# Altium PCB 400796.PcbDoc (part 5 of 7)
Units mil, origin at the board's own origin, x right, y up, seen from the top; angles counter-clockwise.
Board outline 2086.61 x 2086.61 mil, 6 copper layers (Top Layer, Mid Layer 1, Mid Layer 2, Mid Layer 3, Mid Layer 4, Bottom Layer), stack 58.818 mil thick; 313 components, 234 nets, 1244 pads, 2538 vias.
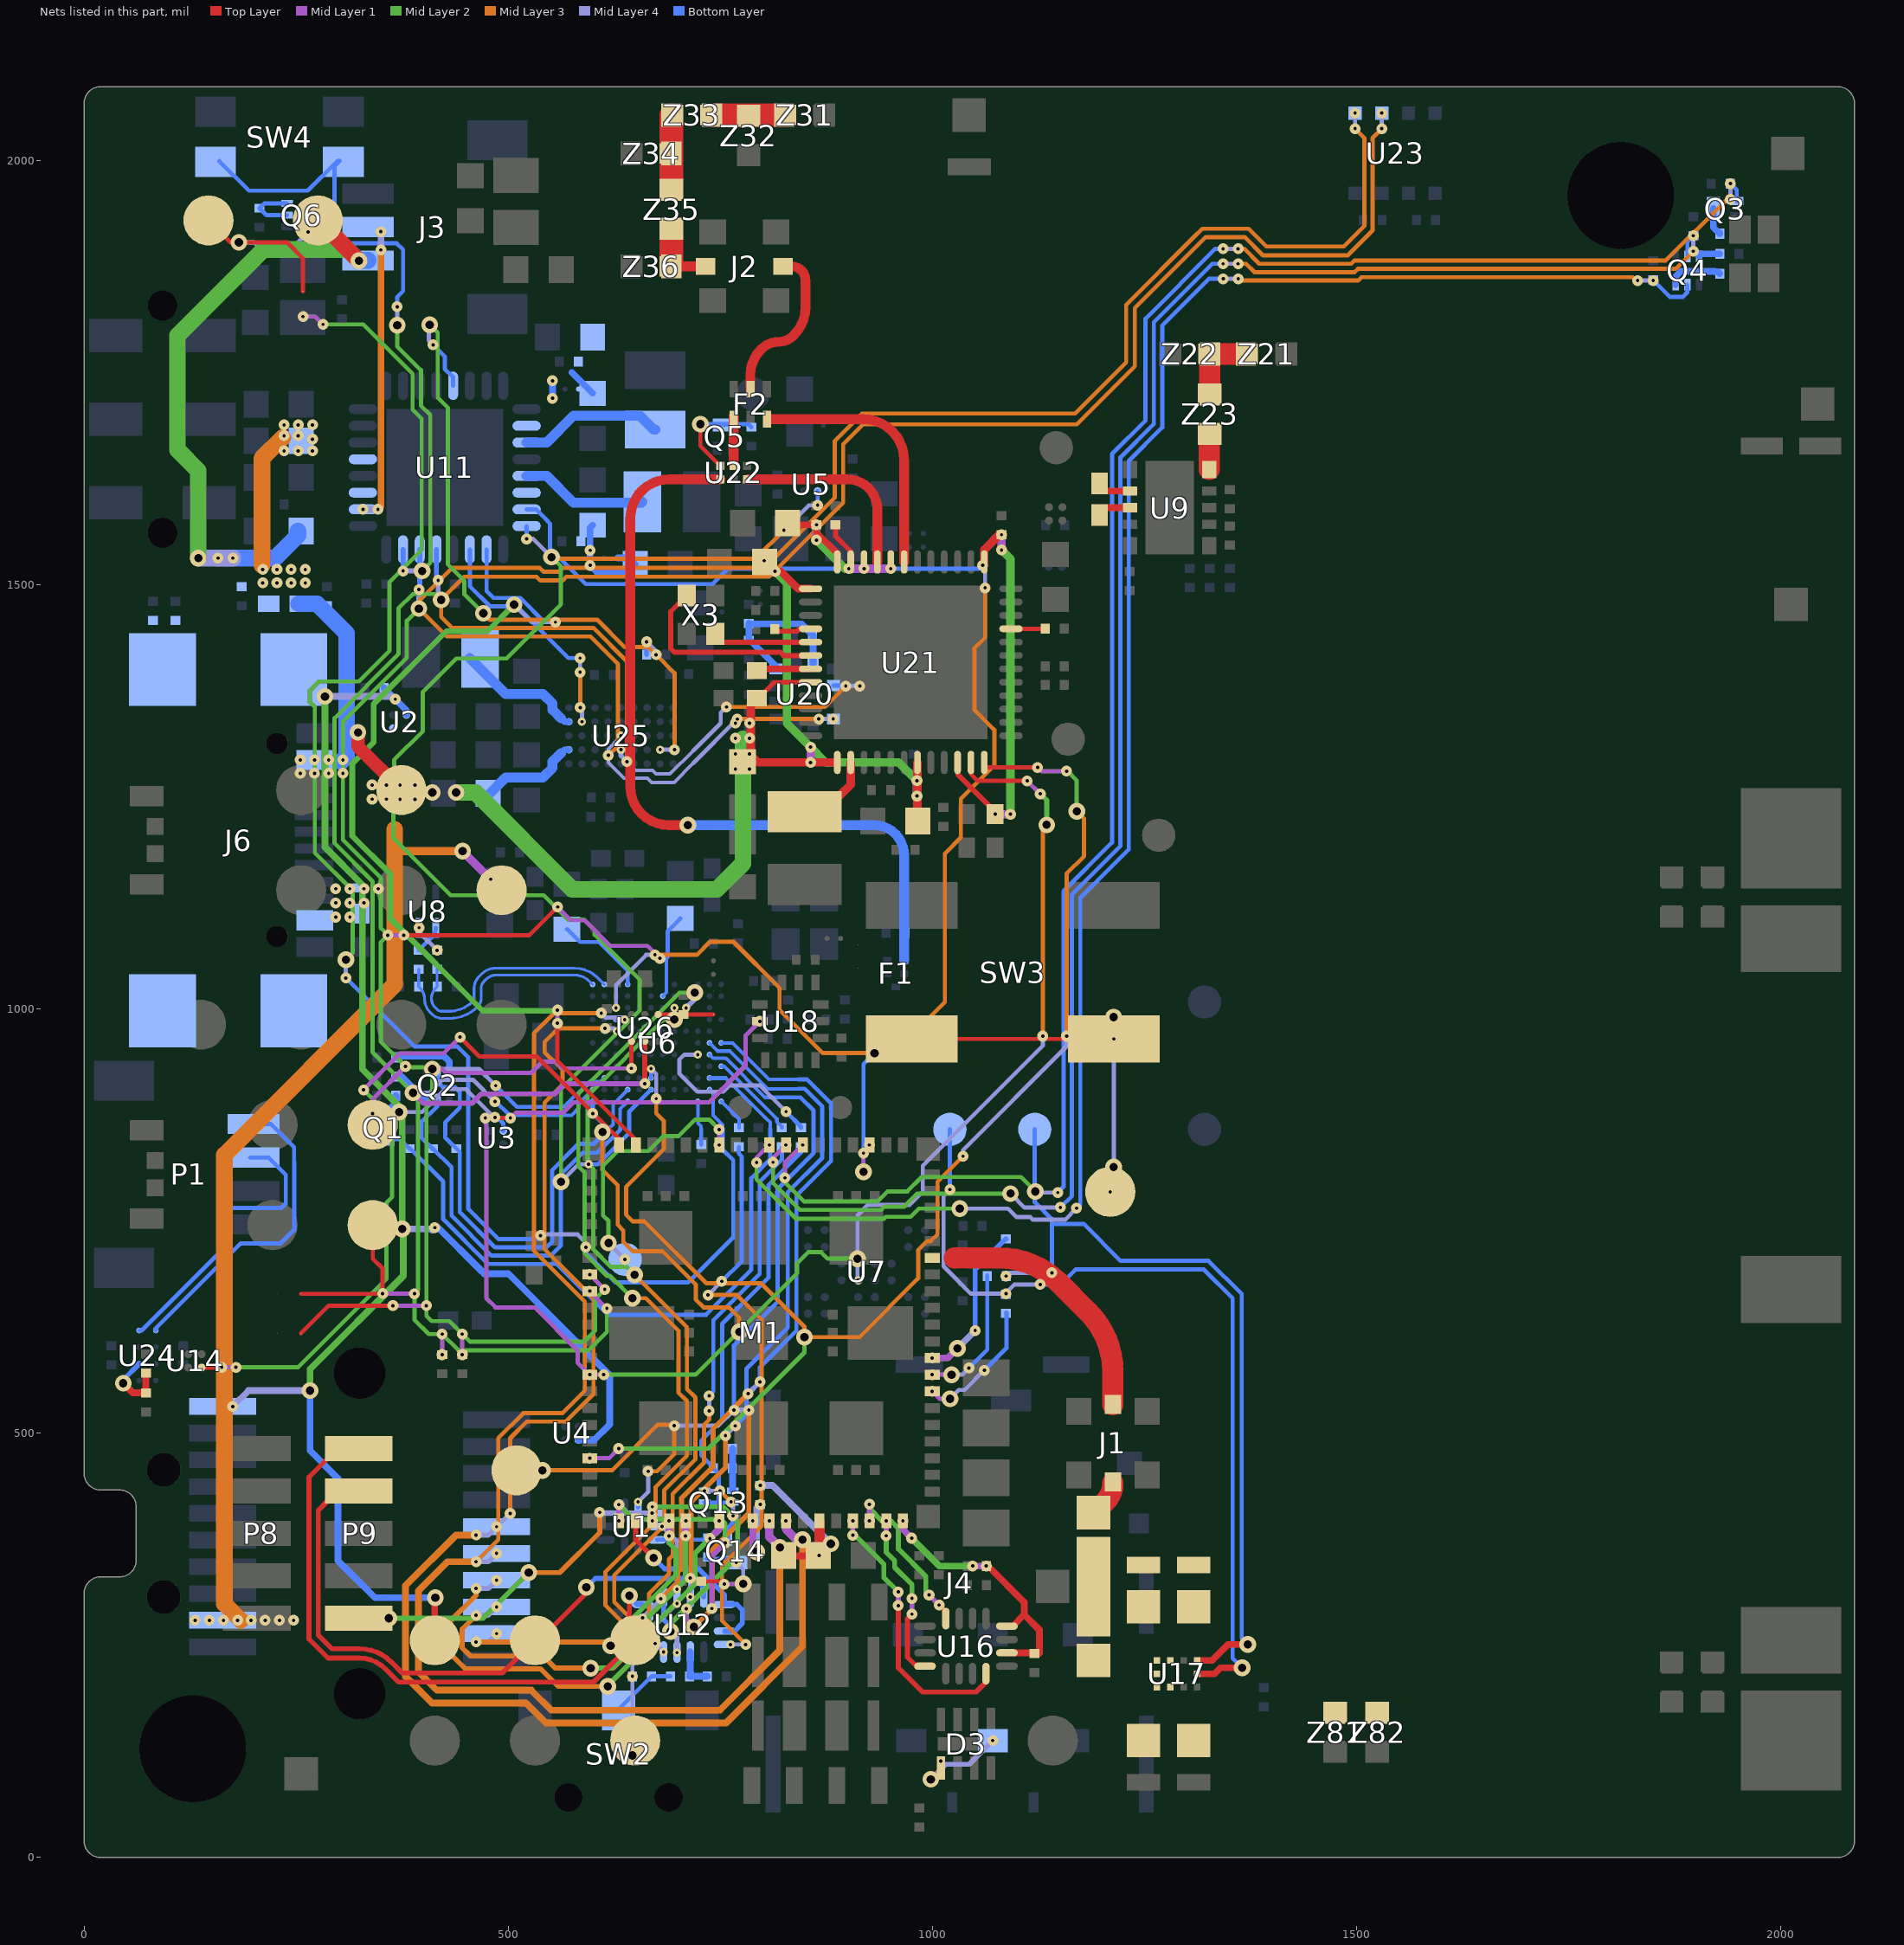
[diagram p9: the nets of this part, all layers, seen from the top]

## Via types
v1: diameter 12.8, hole 3.94, Mid Layer 4 to Bottom Layer, tented both sides, 653 vias
v2: diameter 12.8, hole 3.94, Top Layer to Mid Layer 1, tented both sides, 560 vias
v3: diameter 12.8, hole 3.94, Mid Layer 3 to Mid Layer 4, tented both sides, 388 vias
v4: diameter 19.68, hole 9.84, Mid Layer 1 to Mid Layer 4, tented both sides, 311 vias
v5: diameter 12.8, hole 3.94, Mid Layer 1 to Mid Layer 2, tented both sides, 265 vias
v6: diameter 19.68, hole 9.84, Top Layer to Bottom Layer, tented both sides, 169 vias
v7: diameter 9.84, hole 3.94, Mid Layer 4 to Bottom Layer, tented both sides, 105 vias
v8: diameter 12.8, hole 3.94, Top Layer to Mid Layer 1, tented top, 70 vias
v9: diameter 9.84, hole 3.94, Top Layer to Mid Layer 1, tented both sides, 17 vias

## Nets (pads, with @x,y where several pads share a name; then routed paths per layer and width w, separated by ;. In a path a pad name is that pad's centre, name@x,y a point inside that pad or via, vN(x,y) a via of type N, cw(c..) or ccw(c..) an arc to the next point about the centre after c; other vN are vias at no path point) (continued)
NetC71_2: C71.2 U21.16 | length 44.6
  Top Layer w5.98: C71.2@814.17,1447.43 814.17,1446.84 816,1445.02 840.29,1445.02 841.23,1445.96 843.1,1447.83 U21.16@856.3,1447.83
NetC72_2: C72.2 U21.19 | length 64
  Top Layer w7.87: C72.2@793.11,1398.58 795.13,1400.59 U21.19@856.3,1400.59
NetC87_2: C87.2 C88.2 R26.2 U20.10 U20.12 | length 181.8
  Bottom Layer w7.87: U20.10@815.55,1400.59 815.55,1403.67 783.46,1435.76 R26.2@783.46,1454.33 784.06,1453.74 845.47,1453.74 859.25,1439.96 U20.12@859.25,1406.89
NetC92_2: C92.2 SB10.2 U26.C1 | length 65.1
  Top Layer w4.92: U26.C1@676.7,993.35 676.81,993.24 SB10.2@741.78,993.24
NetC103_2: C103.2 FB1.2 M1.14 R1.1 | length 211
  Top Layer w8: C103.2@827.34,355.52 FB1.2@865.42,355.52
  Top Layer w12: FB1.2@865.42,355.94 v2(866.46,355.94) ; FB1.2@866.81,355.94 M1.14@866.81,396.65
  Mid Layer 1 w8: v2(866.46,355.94) v4(880.18,369.67)
  Mid Layer 4 w8: v1(796.94,438.41) 811.44,438.41 v4(880.18,369.67)
NetCR1_2: CR1.2 F1.4 U22.1 | length 941.3
  Top Layer w11.42: v6(711.61,1216.54) 689.05,1216.54 cw(c689.05,1261.74) 643.84,1261.74 643.84,1577.85 cw(c690.01,1577.85) 690.01,1624.02 U22.1@750,1624.02
  Bottom Layer w11.42: v6(711.61,1216.54) 931.09,1216.54 cw(c931.09,1181.1) 966.53,1181.1 F1.4@966.53,1057.11
NetF2_1: F2.1 U22.5 | length 57.8
  Top Layer w11.42: U22.5@765.75,1641.02 F2.1@765.75,1698.82
NetF2_3: F2.3 U21.7 | length 308
  Top Layer w11.42: F2.3@806.1,1694.88 918.28,1694.88 cw(c918.28,1646.63) 966.54,1646.63 U21.7@966.54,1526.57
NetF2_6: F2.6 J2.1 | length 197.6
  Top Layer w11.42: F2.6@785.43,1730.31 785.43,1747.09 cw(c827.73,1747.09) 797.82,1776.99 798.25,1777.42 cw(c818.88,1756.78) 818.88,1785.97 ccw(c818.88,1809.4) 835.45,1792.83 836.78,1794.16 ccw(c803.96,1826.99) 850.38,1826.99 850.38,1858.31 ccw(c833.59,1858.31) 845.46,1870.18 ccw(c833.99,1858.71) 833.99,1874.93 J2.1@823.92,1874.93
NetJ1_1: J1.1 M1.35 | length 296.3
  Top Layer w25.12: 1026.01,706.64 1078.2,706.64 cw(c1078.2,606.64) 1148.91,677.35 1183.31,642.96 cw(c1112.6,572.24) 1212.6,572.24 J1.1@1212.6,533.86
NetJ1_3: J1.3 Z7.1 | length 44.1
  Top Layer w25.12: Z7.1@1189.72,405.31 1203.3,418.89 ccw(c1180.85,441.34) J1.3@1212.6,441.34
NetJ2_3: J2.3 Z35.1 Z36.1 | length 83.5
  Top Layer w11.42: Z36.1@692.19,1874.93 J2.3@732.58,1874.93
  Top Layer w27.95: Z36.1@692.19,1874.93 Z35.1@692.18,1918.07
NetL1_2: L1.2 U6.B6 | length 100.1
  Bottom Layer w4.13: U6.B6@682.07,1014.96 686.3,1019.19 686.3,1059.33 687.97,1061.01
  Bottom Layer w4.92: 687.97,1061.01 687.97,1091.73 L1.2@702.74,1106.5
NetL2_2: L2.2 U6.A9 | length 108.4
  Bottom Layer w4.92: L2.2@568.88,1093.7 569.86,1093.7 584.8,1078.76 607.19,1078.76 640.73,1045.22 U6.A9@640.73,1028.74
NetL5_1: L5.1 U9.8 | length 38.4
  Top Layer w7.87: L5.1@1196.85,1584.65 1202.76,1590.55 1207.37,1590.55 U9.8@1232.78,1590.55
NetL5_2: L5.2 U9.7 | length 38.4
  Top Layer w7.87: L5.2@1196.85,1616.14 1202.76,1610.24 1207.37,1610.24 U9.7@1232.78,1610.24
NetL6_1: L6.1 U21.26 | length 93.5
  Top Layer w10: L6.1@849.41,1232.15 868.62,1251.36 890.6,1251.36 903.54,1264.31 U21.26@903.54,1290.35
NetM1_2: M1.2 SB6.1 | length 260
  Mid Layer 1 w5.91: v2(630.42,396.65) v5(630.42,415.76) ; v2(739.9,293.4) 739.9,355 v5(755.58,370.67)
  Mid Layer 2 w5.91: v5(630.42,415.76) 647.7,398.48 750.54,398.48 755.58,393.44 v5(755.58,370.67)
NetM1_3: M1.3 U12.5 U12.7 | length 229.6
  Top Layer w5.91: M1.3@650.1,396.65 650.1,374.36 v6(671.32,353.15)
  Bottom Layer w5.91: v6(671.32,353.15) 684.3,340.16 724.31,340.16 754.92,309.55 U12.5@754.92,298.23 769.41,298.23 775.97,291.67 775.97,275.95 766.75,266.73 U12.7@754.92,266.73
NetM1_4: M1.4 U12.1 U12.11 | length 387
  Mid Layer 1 w5.91: v2(669.79,396.65) v5(669.79,413.3)
  Mid Layer 2 w5.91: v5(669.79,413.3) 753.02,413.3 770.25,396.07 770.25,354.65 691.12,275.52 v4(691.12,266.4)
  Mid Layer 4 w5.91: v4(691.12,266.4) 698.82,258.7 v7(698.82,241.43)
  Bottom Layer w5.91: U12.1@683.07,307.09 683.07,280.49 698.82,264.74 U12.11@698.82,242.13 v7(698.82,241.43)
NetM1_10: M1.10 R1.2 | length 106.1
  Mid Layer 1 w8: v2(788.07,396.65) 788.07,364.81 v4(792.64,360.24) ; v4@789.64,357.24 v4@792.64,354.24
  Mid Layer 4 w8: v4@792.64,354.24 v4(792.64,360.24) 792.64,411.67 v1(796.94,415.97)
NetM1_27: M1.27 R27.1 | length 164.8
  Mid Layer 1 w4.92: v2(999.53,549.21) 1008.27,540.47 v4(1020.66,540.47)
  Mid Layer 4 w4.92: v4@1026.67,540.47 v4(1020.66,540.47) 1031.05,550.87 1037.87,550.87 v1(1061.13,574.12)
  Bottom Layer w4.92: v1(1061.13,574.12) 1087.2,600.2 1087.2,642.32 R27.1@1086.61,642.32
NetM1_28: M1.28 R28.1 | length 164.8
  Mid Layer 1 w4.92: v2(999.53,568.9) v4(1022.42,568.9)
  Mid Layer 4 w4.92: v4(1022.42,568.9) 1034.99,568.9 v1(1042.88,576.79)
  Bottom Layer w4.92: v1(1042.88,576.79) 1064.57,598.47 R28.1@1064.57,686.02
NetM1_29: M1.29 R29.1 | length 187.4
  Mid Layer 1 w7.87: v2(999.53,588.58) 1017.96,588.58 v4(1029.38,600)
  Mid Layer 4 w7.87: v4(1029.38,600) 1050.2,620.82 v1(1050.2,621)
  Bottom Layer w5.91: v1(1050.2,621) 1050.2,693.03 1085.91,728.74 R29.1@1086.61,728.74
NetM1_44: M1.44 SW3.2 TP36.1 U6.C10 U11.7 | length 2338
  Top Layer w4.92: SW3.2@975.39,964.57 v2(1213.58,964.57)
  Mid Layer 1 w4.92: v4(918.71,808.12) 918.71,832.57 v2(925.71,839.57) ; v2(1209.43,784.45) 1213.39,788.41 v4(1213.39,813.48) ; v2(1213.58,964.57) v4(1213.58,990.29)
  Mid Layer 3 w4.92: v3(672.79,1063.59) 722.15,1063.59 737.6,1079.03 765.45,1079.03 819.79,1024.69 819.79,998.77 870.75,947.82 v6(931.63,947.82) 941.46,947.82 955.99,962.35 969.12,962.35 1014.46,1007.7 1014.46,1182.95 1033.48,1201.96 1033.48,1247.56 1072.87,1286.96 1072.87,1328.86 1049.47,1352.26 1049.47,1424.87 1062.01,1437.41 v3(1062.01,1496.06)
  Mid Layer 4 w4.92: v7(626.95,1001.18) 626.95,1027.98 662.56,1063.59 v3(672.79,1063.59) ; v4(918.71,808.12) v1(918.71,829.93) ; v1(1059.06,1522.64) 1062.01,1519.68 v3(1062.01,1496.06) ; v4(1213.39,813.48) 1213.58,813.67 v4(1213.58,990.29)
  Bottom Layer w4.92: U11.7@521.65,1588.58 532.48,1588.58 546.26,1574.8 549.1,1571.96 549.1,1542.82 591.43,1500.49 740.65,1500.49 758.86,1518.7 1055.12,1518.7 v1(1059.06,1522.64) ; v1@920.9,828.93 918.71,831.12 918.71,934.9 v6(931.63,947.82)
NetM1_48: M1.48 Q3.1 R44.2 | length 2280.2
  Mid Layer 1 w4.92: v5(825.95,800.89) 825.95,818.55 v2(846.97,839.57)
  Mid Layer 2 w4.92: v5(825.95,800.89) 825.95,795.54 848.37,773.12 935.35,773.12 947.08,784.85 970.32,784.85 987.28,801.8 1104.11,801.8 v4(1121.06,784.85)
  Mid Layer 3 w4.92: v3(1360.24,1895.67) 1367.32,1895.67 1385.03,1877.95 1493.39,1877.95 1497.33,1881.89 1864.17,1881.89 1936.42,1954.13 v3(1940.35,1954.13)
  Mid Layer 4 w4.92: v4(1121.06,784.85) 1122.37,783.54 v1(1147.64,783.54) ; v1(1342.52,1895.67) v3(1360.24,1895.67) ; v3(1940.35,1954.13) v1(1940.35,1972.44)
  Bottom Layer w4.92: v1(1147.64,783.54) 1154.53,790.43 1154.53,1138.78 1211.61,1195.87 1211.61,1653.82 1250.98,1693.19 1250.98,1813.27 1333.38,1895.67 v1(1342.52,1895.67) ; v1(1940.35,1972.44) 1947.83,1964.96 Q3.1@1947.83,1951.77
NetM1_49: M1.49 Q4.5 R46.2 | length 2230.4
  Mid Layer 1 w4.92: v5(812.1,819.26) 812.1,824.38 v2(827.28,839.57)
  Mid Layer 2 w4.92: v5(812.1,819.26) 812.1,794.68 843.6,763.18 939.33,763.18 943.22,767.07 966.75,767.07 982.01,782.33 v4(1091.91,782.33)
  Mid Layer 3 w4.92: v3(1360.24,1877.95) 1369.61,1877.95 1379.45,1868.11 1497.47,1868.11 1501.4,1872.05 1875.98,1872.05 v3(1896.65,1892.72)
  Mid Layer 4 w4.92: v4(1091.91,782.33) 1108.39,765.84 1150.61,765.84 v1(1150.79,766.02) ; v1(1342.52,1877.95) v3(1360.24,1877.95) ; v3(1896.65,1892.72) v1(1896.65,1911.02)
  Bottom Layer w4.92: v1(1150.79,766.02) 1164.37,779.6 1164.37,1134.7 1221.46,1191.79 1221.46,1649.75 1260.83,1689.12 1260.83,1809.2 1329.58,1877.95 v1(1342.52,1877.95) ; Q4.5@1889.76,1886.81 1889.76,1904.13 v1(1896.65,1911.02)
NetM1_50: M1.50 Q4.2 R45.2 | length 2206.4
  Mid Layer 1 w4.92: v5(792.72,818.89) 792.72,824.69 v2(807.6,839.57)
  Mid Layer 2 w4.92: v5(792.72,818.89) 792.72,799.02 839.07,752.67 942.74,752.67 944.93,754.86 974.13,754.86 983.84,764.57 v4(1032.19,764.57)
  Mid Layer 3 w4.92: v3(1360.27,1860.2) 1362.21,1858.27 1501.54,1858.27 1505.48,1862.2 1825.03,1862.2 1828.97,1858.26 v3(1831.1,1858.26)
  Mid Layer 4 w4.92: v4(1032.19,764.57) 1089.09,764.57 1099.09,754.57 1115.32,754.57 1118.3,751.6 1156.22,751.6 v1(1169.74,765.12) ; v1(1342.56,1860.2) v3(1360.27,1860.2) ; v3(1831.1,1858.26) v1(1849.41,1858.26)
  Bottom Layer w4.92: v1(1169.74,765.12) 1170.63,765.12 1174.21,768.7 1174.21,1130.63 1231.3,1187.71 1231.3,1645.67 1270.67,1685.04 1270.67,1805.12 1325.75,1860.2 v1(1342.56,1860.2) ; R45.2@1849.41,1858.65 1868.99,1839.07 1884.44,1839.07 1889.47,1844.1 1889.47,1853.05 Q4.2@1889.76,1853.35
NetM1_53: M1.53 TP23.1 | length 300
  Mid Layer 1 w4.92: v2(748.54,839.57) v5(748.54,857.88)
  Mid Layer 2 w4.92: v4(618.12,724.02) 618.12,750.09 611.59,756.63 611.59,815.23 628.78,832.43 665.09,832.43 682.56,849.9 700.61,849.9 709.72,859 720.3,869.58 736.84,869.58 747.42,859 v5(748.54,857.88)
  Mid Layer 4 w4.92: v4@621.12,721.02 v1(637.42,704.72)
  Bottom Layer w4.92: v1(637.42,704.72) TP23.1@637.8,704.72
NetM1_59: M1.59 U14.B2 | length 884.4
  Top Layer w5: U14.B2@138.56,577.34 162.13,577.34 v2(162.35,577.57) ; v2(443.14,966.77) 465.99,943.92 533.53,943.92 557,920.45 618.45,859 630.43,847.02 M1.59@630.43,839.57
  Mid Layer 1 w5: v2(162.35,577.57) v5(179.09,577.57) ; v5(329.5,904.54) 372.51,947.59 423.97,947.59 v2(443.14,966.77)
  Mid Layer 2 w5: v5(179.09,577.57) 252.17,577.57 356.46,681.86 356.46,771.7 363.23,778.46 363.23,859.19 347.88,874.54 347.88,886.16 v5(329.5,904.54)
NetP1_3: P1.3 U24.A2 | length 346
  Bottom Layer w4.92: U24.A2@64.96,621.06 68.07,621.06 161.91,714.9 161.91,760.93 166.51,765.54 232.67,765.54 237.8,770.66 237.8,804.53 217.52,824.8 P1.3@195.87,824.8
NetP1_4: P1.4 U24.A1 | length 360.1
  Bottom Layer w4.92: U24.A1@84.65,621.06 84.65,623.71 184.36,723.43 231.3,723.43 247.64,739.76 247.64,819.78 247.54,819.88 247.54,836.96 220.32,864.17 P1.4@209.65,864.17
NetP9_10: P9.10 R3.1 TP1.1 U2.B2 U3.B2 U4.B2 | length 2104.4
  Top Layer w7.87: TP1.1@413.39,255.91 413.39,305.46 v6(414,306.08)
  Mid Layer 2 w7.87: v6(266.32,550.11) 266.32,575.37 376.27,685.33 376.27,739.19 v4(374.91,740.55) 374.91,873.57 370.21,878.27 370.21,886.67 328.15,928.73 328.15,1146.14 283.96,1190.33 v4(283.96,1368.11)
  Mid Layer 4 w4.92: v4@370.21,878.27 v4@370.8,878.87 ; v4(371.39,878.27) 398.35,878.27 425.46,905.39 450.13,905.39 477.66,877.86 483.47,872.05 v1(484.25,872.05)
  Mid Layer 4 w7.87: v1(175.2,531.5) 193.81,550.11 v6(266.32,550.11) ; v4(283.96,1368.11) 361.22,1368.11 v1@365.16,1364.17 ; v4(374.91,740.55) 408.97,740.55 410.39,739.13 v1(413.39,742.13)
  Bottom Layer w4.92: v1(484.25,872.05) 487.2,872.05 494.09,865.16 U3.B2@494.09,856.3
  Bottom Layer w7.87: v6(266.32,550.11) 266.32,479.53 299.21,446.64 299.21,349.73 342.86,306.08 v6(414,306.08) ; R3.1@353.74,1377.95 379.92,1351.77 U2.B2@379.92,1346.46 ; v1(413.39,742.13) 417.32,742.13 467.03,692.42 471.47,687.98 500.01,687.98 619.59,568.41 619.59,510.33 601.38,492.13 U4.B2@582.68,492.13
  other v1: 366.83,1364.86
NetQ1_1: Q1.1 R41.2 U6.J2 | length 834.5
  Bottom Layer w4.13: 756.44,918.5 803.73,871.21 808.63,866.31 808.63,859
  Bottom Layer w4.92: Q1.1@361.22,846.46 372.64,846.46 R41.2@383.86,835.24 ; R41.2@384.26,835.63 423.23,796.66 423.23,752.23 476.15,699.3 557.33,699.3 617.04,639.59 733.21,639.59 786.38,692.75 786.38,800.53 808.63,822.79 808.63,859 ; U6.J2@737.19,918.5 756.44,918.5
NetQ1_3: Q1.3 R20.1 | length 29.9
  Bottom Layer w7.87: Q1.3@352.36,874.02 367.52,889.17 R20.1@367.52,897.64
NetQ2_2: Q2.2 R38.2 U6.K9 | length 554.7
  Bottom Layer w4.13: 618.78,859 623.53,863.75 623.53,887.53 631.18,895.18 U6.K9@640.73,904.72
  Bottom Layer w4.92: Q2.2@416.78,926.55 416.78,913.75 422.68,907.85 437.06,907.85 442.86,902.05 442.86,883.24 425.67,866.05 425.67,851.46 425.59,851.38 425.59,848.52 ; 425.67,848.52 442.91,831.28 442.91,760.38 484.31,718.99 544.79,718.99 551.82,726.01 551.82,758.34 551.82,809.99 582.81,840.99 600.77,840.99 618.78,859
NetQ2_3: Q2.3 R21.1 | length 78.6
  Bottom Layer w7.87: R21.1@367.52,942.91 367.52,944.39 424.16,944.39 430.56,937.99 Q2.3@430.56,926.55
NetQ2_5: Q2.5 R42.2 U6.L9 | length 525.6
  Bottom Layer w4.13: 631.88,859 631.88,882.09 U6.L9@640.73,890.95
  Bottom Layer w4.92: R42.2@410.98,834.8 397.64,848.14 397.64,866.45 416.78,885.6 Q2.5@416.78,893.08 ; R42.2@411.42,835.24 433.07,813.58 433.07,756.3 480.23,709.14 550.03,709.14 562.04,721.15 562.04,754.31 562.04,805.03 587.49,830.47 604.79,830.47 631.88,857.56 631.88,859
NetQ2_6: Q2.6 R19.1 | length 46.7
  Bottom Layer w7.87: R19.1@367.52,920.28 374.47,920.28 401.67,893.08 Q2.6@403,893.08
NetQ3_3: Q3.3 R12.1 | length 33.9
  Bottom Layer w7.87: Q3.3@1920.28,1942.91 1920.28,1920.87 R12.1@1927.76,1913.39 R12.1@1927.76,1914.69
NetQ4_3: Q4.3 R14.1 | length 69.4
  Bottom Layer w7.87: Q4.3@1875.98,1853.35 1875.98,1862.92 1882.16,1869.09 1897.37,1869.09 ; 1893.43,1869.09 1921.77,1869.09 1922.75,1868.11 1926.38,1868.11 1927.76,1866.73 R14.1@1927.76,1866.14
NetQ4_6: Q4.6 R13.1 | length 27.2
  Bottom Layer w7.87: Q4.6@1903.54,1886.81 1903.54,1889.76 R13.1@1927.76,1889.76
NetQ5_3: Q5.3 R62.2 U22.6 | length 120.9
  Top Layer w4.92: v6(726.38,1688.98) 726.38,1663.39 U22.6@750,1639.76
  Bottom Layer w4.92: v6(726.38,1688.98) 753.94,1688.98 Q5.3@754.92,1687.99 ; Q5.3@754.92,1688.98 782.87,1688.98 R62.2@786.42,1685.43
NetQ6_2: Q6.2 Q6.3 R64.1 | length 70.7
  Bottom Layer w4.92: Q6.2@239.33,1935.22 215.12,1935.22 R64.1@206.85,1943.49 212.37,1949 Q6.3@239.33,1949
NetQ6_6: Q6.6 SB7.2 TP35.1 | length 270.3
  Top Layer w4.92: TP35.1@146.68,1929.13 172.66,1903.16 v6(182.53,1903.16) 239.21,1903.16 258.09,1884.28 SB7.2@258.09,1845.69
  Mid Layer 4 w4.92: v6(182.53,1903.16) 200.57,1903.16 205.19,1898.53 247.24,1898.53 v7(263.98,1915.27)
  Bottom Layer w4.92: v7(263.98,1915.27) 270.15,1921.44 Q6.6@272.8,1921.44
NetQ13_2: Q13.2 Q13.5 R16.2 R107.1 R108.1 U1.5 | length 619.6
  Bottom Layer w4.92: U1.5@675.4,374.26 675.55,374.41 734.2,374.41 748.03,388.25 748.03,418.31 ; Q13.2@731.3,418.31 748.03,418.31 ; Q13.5@764.76,418.31 748.03,418.31 ; R16.2@844.97,837.4 844.97,830.82 806.81,792.66 806.81,683.45 752.08,628.72 752.08,515.95 727.49,491.36 727.49,473.88 741.84,459.53 R107.1@741.84,458.82 748.03,452.63 748.03,418.31
  Bottom Layer w5.91: Q13.5@764.76,418.31 Q13.5@765.71,419.25
NetQ13_3: Q13.3 Q13.6 Q14.1 | length 86.1
  Mid Layer 3 w4.92: v3(749.52,432.09) v3(762.61,419)
  Mid Layer 4 w4.92: v7(731.3,432.09) v3(749.52,432.09) ; v3(762.61,419) 764.76,416.84 v1(764.76,402.53)
  Bottom Layer w4.92: Q14.1@758.86,375 758.86,388.78 764.76,394.69 v1(764.76,402.53) Q13.6@764.76,404.53
NetQ13_4: Q13.4 R106.2 R107.2 | length 49.8
  Bottom Layer w8: R106.2@764.28,481.68 R107.2@764.28,458.82 764.28,432.57 Q13.4@764.76,432.09
NetQ14_3: Q14.3 R2.1 R108.2 | length 116.9
  Top Layer w4.92: R2.1@727.55,325.5 751.28,325.5 v2(754.61,322.16)
  Mid Layer 1 w4.92: v2(754.61,322.16) v4@775.77,322.16 ; v4@775.77,321.17 v4(776.94,322.35)
  Mid Layer 4 w4.92: v1(768.73,347.44) 776.94,339.23 v4(776.94,322.35)
  Bottom Layer w4.92: R108.2@733.41,351.97 764.2,351.97 v1(768.73,347.44)
NetR4_2: R4.2 U12.8 | length 699.5
  Mid Layer 3 w4.92: v3(735.39,662.74) 769.53,662.74 798.69,633.57 798.69,390.92 751.82,344.04 751.82,279 v3(779.83,250.98)
  Mid Layer 4 w4.92: v3(735.39,662.74) v1(751.55,678.9) ; v7(761.92,250.98) v3(779.83,250.98)
  Bottom Layer w4.92: v1(751.55,678.9) 775.24,702.59 775.24,825.91 771.84,829.31 R4.2@771.84,837.4
NetR5_2: R5.2 R15.1 U24.C2 | length 85.8
  Top Layer w6: v6@45.95,559.14 v6(46.24,558.84)
  Top Layer w8: v6(46.24,558.84) 57.53,547.55 R15.1@72.92,547.55 72.97,547.61 R5.2@72.97,570.96
  Bottom Layer w6: v6(46.24,558.84) 46.24,562.98 U24.C2@64.96,581.69
NetR6_2: R6.2 U12.12 | length 667.3
  Mid Layer 3 w4.92: v3(673.09,252.14) 665.83,259.4 665.83,310.85 689.4,334.43 689.4,351.62 693.81,356.03 693.81,428.34 730.74,465.28 730.74,509.71 736.76,515.73 v3(736.76,526.22)
  Mid Layer 4 w4.92: v3(673.09,252.14) v7(683.07,242.13) ; v3(736.76,526.22) v1(736.76,543.89)
  Bottom Layer w4.92: v1(736.76,543.89) 741.76,548.88 741.76,633.04 796.36,687.64 796.36,796.13 822.48,822.25 R6.2@822.48,837.4
NetR11_2: R11.2 U6.L3 | length 52.6
  Bottom Layer w4.13: U6.L3@723.41,890.95 723.41,865.56 727.38,861.59 727.38,859
  Bottom Layer w4.92: R11.2@727.38,839.96 727.38,859
NetR17_1: R17.1 R32.2 U12.10 | length 50
  Bottom Layer w8: U12.10@714.57,242.13 714.57,214.45 R17.1@713.58,213.46 R32.2@734.53,213.46
NetR17_2: R17.2 R18.1 SW2.2 | length 78.6
  Bottom Layer w4.92: SW2.2@629.92,173.23 629.92,174.48 R18.1@668.9,213.46 R17.2@691.14,213.46
NetR18_2: R18.2 TP28.1 U1.4 U12.2 | length 281.8
  Mid Layer 4 w4.92: v6(646.39,120.22) v1(646.39,213.53) 646.39,246.66 v7(698.82,299.09) ; v7(681.4,390.01) 698.82,372.59 v7(698.82,316.09)
  Bottom Layer w4.92: v1(646.39,213.53) R18.2@646.46,213.46
NetR31_2: R31.2 U8.7 | length 34.8
  Mid Layer 4 w4.92: v1(394.95,1095.6) ccw(c407.8,1095.6) 398.71,1086.51 v1(416.21,1069.01)
NetR34_2: R34.2 U8.6 | length 32.9
  Bottom Layer w4.92: R34.2@394.47,1069.01 394.58,1069.01 404.71,1079.14 ; 405.49,1079.93 409.82,1084.26 ccw(c398.68,1095.4) U8.6@414.44,1095.4
NetSB6_2: SB6.2 TP5.1 U1.2 U6.G2 | length 1276.8
  Top Layer w4.92: TP5.1@509.68,456.22 v6(540.35,456.22)
  Top Layer w5.91: v2(709.88,293.09) 712.34,293.09 SB6.2@712.34,293.4
  Mid Layer 1 w5.91: v2@709.92,293.05 v2(709.88,293.09) 709.88,280.73 v4(718.88,271.73)
  Mid Layer 3 w4.92: v6(540.35,456.22) 622.47,456.22 676.12,509.87 694.52,509.87 v3(695.67,508.72) 695.67,475.24 675.49,455.06 v3(664.81,455.06)
  Mid Layer 3 w5.91: v4(718.88,271.73) 740.54,293.39 740.54,362.66 783.5,405.63 783.5,422.88 v3(783.5,527.16)
  Mid Layer 4 w4.92: v7(653,418.98) 664.81,430.79 v3(664.81,455.06) ; v3(695.67,508.72) 747.53,508.72 v1(765.97,527.16)
  Mid Layer 4 w5.91: v1(765.97,527.16) v3(783.5,527.16)
  Bottom Layer w4.13: U6.G2@737.19,946.06 741.42,941.83 756,941.83 756.44,941.39 757.17,941.39 802.88,895.68 842,895.68
  Bottom Layer w4.92: v6@540.01,455.88 v6(540.35,456.22) ; U1.2@653,412.41 v7(653,418.98) ; v1(765.97,527.16) 765.97,603.57 817.58,655.18 817.58,787.85 859.75,830.01 859.75,880.34 844.41,895.68 842,895.68
NetSB7_1: SB7.1 U6.K2 | length 1909.1
  Mid Layer 1 w4.92: v2(258.12,1815.67) 272.53,1815.67 v5(281.69,1806.5)
  Mid Layer 2 w4.92: v5(281.69,1806.5) 328.92,1806.5 387.23,1748.2 387.23,1706.15 397.94,1695.44 397.94,1540.82 360.12,1503.01 360.12,1421.97 323.98,1385.83 276.86,1385.83 266.27,1375.24 266.27,1361.22 271.96,1355.53 271.96,1183.94 316.66,1139.24 316.66,1066.07 v4(308.62,1058.03)
  Mid Layer 4 w4.92: v1(308.62,1036.34) v4(308.62,1058.03) ; v1(538.02,732.79) 539.48,734.25 581.79,734.25 591.43,724.61 v1(591.43,719.14)
  Bottom Layer w4.13: U6.K2@737.19,904.72 741.42,900.49 741.42,886.99 741.42,874.69 752.66,863.45 752.66,859
  Bottom Layer w4.92: v1@308.62,1035.34 v1@309.08,1034.89 ; v1(308.62,1036.34) 389.26,955.71 439.96,955.71 452.76,942.91 452.76,764.46 488.38,728.83 534.05,728.83 v1(538.02,732.79) ; v1(591.43,719.14) 591.43,712.41 626.29,677.55 711.9,677.55 727.85,693.51 765.08,730.74 765.08,821.75 752.66,834.17 752.66,859
NetU6_F1: U6.F1 U12.15 | length 857
  Mid Layer 3 w5.91: v3(679.9,304.91) 699.74,324.76 699.74,335.91 704.23,340.4 704.23,423.4 741.4,460.56 741.4,505.27 v3(782.6,546.46)
  Mid Layer 4 w5.91: v7(658.46,282.48) 679.9,303.91 v3(679.9,304.91) ; v3(782.6,546.46) v1(796.62,560.49)
  Bottom Layer w4.13: U6.F1@750.97,959.84 751.06,959.74 764.43,959.74 807.2,916.97 842,916.97
  Bottom Layer w4.92: v1(796.62,560.49) 796.62,577.73 839.65,620.75 839.65,779.86 880.37,820.58 880.37,888.67 852.07,916.97 842,916.97
NetU6_F2: U6.F2 U12.3 | length 806.2
  Mid Layer 3 w5.91: v3(714.57,329.18) 715.31,329.93 715.31,418.75 755.98,459.43 v3(755.98,497.12)
  Mid Layer 4 w4.92: v3(755.98,497.12) v1(767.52,508.66)
  Mid Layer 4 w5.91: v7(714.57,307.09) v3(714.57,329.18)
  Bottom Layer w4.13: U6.F2@737.19,959.84 746.73,950.3 761.07,950.3 805.55,905.82 842,905.82
  Bottom Layer w4.92: v1(767.52,508.66) 780.71,521.85 780.71,575.73 829.43,624.45 829.43,783.89 870.12,824.58 870.12,884.84 849.14,905.82 842,905.82
NetU9_5: U9.5 Z23.1 | length 41.4
  Top Layer w25.12: U9.5@1326.28,1635.57 1326.28,1676.28 Z23.1@1326.77,1676.77
NetU12_13: U12.13
NetU21_9: U21.9 U22.3 | length 234.8
  Top Layer w11.42: U22.3@782.48,1624.02 899.61,1624.02 cw(c899.61,1588.58) 935.04,1588.58 U21.9@935.04,1526.57
NetU21_17: U21.17 X3.1 | length 118
  Top Layer w6: X3.1@739.96,1436.02 743.9,1432.09 U21.17@856.3,1432.09
NetU21_18: U21.18 X3.3 | length 239.9
  Top Layer w6: X3.3@710.43,1487.2 710.43,1485.24 702.61,1477.41 700.64,1477.41 691.46,1468.23 691.46,1424.56 695.88,1420.13 695.99,1420.13 696.03,1420.09 820.94,1420.09 824.69,1416.34 U21.18@856.3,1416.34
NetZ1_2: Z1.2 Z2.2 Z81.1 Z82.1
NetZ5_1: Z5.1 Z6.1 Z7.2 | length 85.8
  Top Layer w25.12: Z5.1@1189.37,277.17 Z7.2@1189.37,363.01
NetZ21_1: Z21.1 Z22.1 Z23.2 | length 89.5
  Top Layer w25.12: Z23.2@1326.77,1724.8 1326.77,1771.26 Z22.1@1327.17,1771.65 Z21.1@1369.68,1771.65
NetZ31_1: Z31.1 Z32.2 Z33.2 | length 130.4
  Top Layer w27.95: Z32.2@785.43,2053.15 Z33.2@740.21,2053.15 Z31.1@825.39,2053.15
NetZ33_1: Z33.1 Z34.1 Z35.2 | length 87.1
  Top Layer w27.95: Z35.2@692.18,1966.1 Z34.1@692.18,2007.92 Z33.1@692.18,2053.15
nPM60_ENABLE: R9.2 U11.29 U25.B2 | length 844.6
  Mid Layer 2 w4.92: v4(407.48,1806.1) 416.83,1796.75 416.83,1720.41 428.72,1708.52 428.72,1523.98 442.31,1510.39 448.08,1504.63 448.08,1488.68 v4(470.59,1466.17)
  Mid Layer 3 w4.92: v4(470.59,1466.17) 478.29,1458.47 604.81,1458.47 637.09,1426.18 665.35,1426.18 v3(674.21,1417.32) 695.91,1395.62 v3(695.91,1305.32)
  Mid Layer 4 w4.92: v4@406.5,1804.13 406.5,1787.4 v1(411.42,1782.48) ; v1(662.99,1432.48) 674.21,1421.26 v3(674.21,1417.32) ; v7(678.94,1305.32) v3(695.91,1305.32)
  Bottom Layer w4.92: v1(411.42,1782.48) 425.2,1768.7 425.2,1754.03 435.04,1744.19 U11.29@435.04,1734.25 ; R9.2@662.99,1417.32 v1(662.99,1432.48)
nPM60_READY: U11.11 U25.H4 | length 283.4
  Mid Layer 3 w4.92: v3(584.65,1396.65) 584.84,1396.46 v3(584.84,1355.11)
  Mid Layer 4 w4.92: v3(584.65,1396.65) v1(584.65,1413.39) ; v7(586.81,1338.39) v3@586.81,1355.11
  Bottom Layer w4.92: U11.11@454.72,1541.34 454.72,1498.03 478.44,1474.31 510.03,1474.31 570.96,1413.39 v1(584.65,1413.39)
nPM1300_INT: M1.58 U11.10 | length 1137.6
  Top Layer w4.92: v2(558,983.07) 558,938.34 650.12,846.23 M1.58@650.12,839.57
  Mid Layer 1 w4.92: v2(558,983.07) v5(558,998.47)
  Mid Layer 2 w6.69: v4(506.78,1476.32) 475.46,1445 427.09,1445 341.54,1359.44 341.54,1314.38 316.14,1288.98 316.14,1203.83 360.97,1158.99 360.97,1106.61 469.78,997.8 557.34,997.8 v5(558,998.47)
  Mid Layer 4 w4.92: v4(506.78,1476.32) 527.39,1455.71 v1(555.53,1455.71)
  Bottom Layer w4.92: U11.10@474.41,1541.34 474.41,1492.27 482.52,1484.15 514.11,1484.15 542.55,1455.71 v1(555.53,1455.71)
NTC: J3.2 U11.18 | length 346.4
  Mid Layer 3 w7.87: v3(346.46,1588.58) 349.9,1592.03 v3(349.9,1894.19)
  Mid Layer 4 w7.87: v1(328.74,1588.58) v3(346.46,1588.58) ; v3(349.9,1894.19) v1(349.9,1915.85)
P0.08/TRACEDATA3: M1.12 P9.15 U6.E10 | length 1712.9
  Mid Layer 1 w9.84: v2(827.27,396.65) 827.27,386.86 839.67,374.46 v4(846.78,374.46)
  Mid Layer 3 w4.92: v3(502.24,405.36) 502.24,494.1 521.83,513.69 568.02,513.69 600.4,546.07 600.4,658.83 542.75,716.48 542.75,889.39 557,903.64 563.86,910.5 563.86,928.52 557,935.38 553.05,939.33 551.98,939.33 542.75,948.57 542.75,960.95 558.77,976.96 v3(613.97,976.96)
  Mid Layer 3 w8: v3(462.13,379.92) 438.45,379.92 378.94,320.41 378.94,213.25 410.17,182.02 520.78,182.02 544.21,158.59 756.67,158.59 846.78,248.7 v4(846.78,374.46)
  Mid Layer 4 w4.92: v1(486.22,389.73) 486.62,389.73 v3(502.24,405.36) ; v3@612.97,976.96 v3@613.47,976.46 ; v3(613.97,976.96) 624.61,976.96 v7(627.95,973.62)
  Mid Layer 4 w6: v3(462.13,379.92) 476.41,379.92 v1(486.22,389.73)
P0.09/TRACEDATA2: M1.11 P9.16 U6.D10 | length 1695.5
  Mid Layer 1 w9.84: v2(807.58,396.65) 807.58,377.8 v4(820.08,365.3)
  Mid Layer 3 w4.92: v3(462.13,348.46) 488.29,374.63 488.29,494.18 517.67,523.57 563.88,523.57 590.32,550 590.32,654.92 530.26,714.97 530.26,971.23 553.95,994.92 557,994.92 v3(609.63,994.92)
  Mid Layer 3 w8: v3(462.13,348.46) 428.33,348.46 393.99,314.12 393.99,219.14 415.97,197.16 527.08,197.16 550.71,173.53 749.45,173.53 820.08,244.17 v4(820.08,365.3)
  Mid Layer 4 w4.92: v3(609.63,994.92) 614.82,989.73 634.77,989.73 v7(637.22,987.28)
  Mid Layer 4 w6: v3(462.13,348.46) 476.41,348.46 v1(486.22,358.27)
  Bottom Layer w4.92: U6.D10@626.95,987.4 v7@637.1,987.4
  Bottom Layer w9.84: v7@637.1,987.4 v7(637.22,987.28)
P0.10/TRACEDATA1: M1.8 P9.17 U6.C5 | length 1550.1
  Mid Layer 1 w8: v5(737.55,375.91) 748.53,386.89 v2(748.53,396.65)
  Mid Layer 2 w4.92: v4(648.92,686.75) 639.68,695.98 620.72,695.98 600.28,716.43 600.28,811.27 593.67,817.88 593.67,859 593.67,897.78 683.23,987.34 v4(695.85,987.34)
  Mid Layer 2 w6: v4(617.27,201.63) 617.27,202.88 650.89,236.5 650.89,252.8 720.23,322.14 720.23,358.59 v5(737.55,375.91)
  Mid Layer 3 w4.92: v4(617.27,201.63) 654.9,239.26 654.9,271.14 624.83,301.21 624.83,332.51 683.73,391.41 683.73,432.53 720.7,469.5 720.7,542.04 710.63,552.11 710.63,625.04 v4(648.92,686.75)
  Mid Layer 3 w6: v3(462.13,316.96) 462.13,308.95 430.73,277.55 430.73,241.03 449.32,222.44 538.03,222.44 558.84,201.63 v4(617.27,201.63)
  Mid Layer 4 w6: v3(462.13,316.96) 476.41,316.96 v1(486.22,326.77) ; v4(695.85,987.34) v7(695.85,1001.18)
P0.11/TRACEDATA0: M1.6 P9.18 U6.C4 | length 1506.9
  Mid Layer 1 w8: v5(708.98,378.95) v2@708.98,396.65
  Mid Layer 2 w4.92: v4(646.3,659.13) 634.09,671.34 634.09,671.55 620.35,685.3 616.53,685.3 590.08,711.74 590.08,807.03 582.53,814.58 582.53,859 582.53,899.86 701.81,1019.14 v4(719.64,1019.14)
  Mid Layer 2 w6: v4(597.16,223.16) 621.94,223.16 639.79,241.01 639.79,258.04 708.98,327.22 v5(708.98,378.95)
  Mid Layer 3 w4.92: v4(597.16,223.16) 624.61,223.16 644.71,243.26 644.71,266.95 614.58,297.08 614.58,336.78 673.66,395.87 673.66,436.72 710.59,473.65 710.59,537.93 700.6,547.91 700.6,620.71 662.18,659.13 v4(646.3,659.13)
  Mid Layer 3 w6: v3(462.13,285.47) 445.74,269.08 445.74,247.1 455.49,237.36 541.3,237.36 555.5,223.16 v4(597.16,223.16)
  Mid Layer 4 w6: v3(462.13,285.47) 476.41,285.47 v1(486.22,295.28) ; v7(709.63,1001.18) 719.64,1011.19 v4(719.64,1019.14)
  other v2: 709.16,396.65
P0.12/TRACECLK: M1.5 P9.19 | length 370.9
  Mid Layer 1 w8: v5(689.47,378.95) v2(689.47,396.65)
  Mid Layer 2 w6: v4(620.56,249.43) 620.56,255.92 697.5,332.86 697.5,362.65 689.47,370.68 v5(689.47,378.95)
  Mid Layer 3 w6: v3(462.13,253.97) 527.19,253.97 616.02,253.97 v4(620.56,249.43)
  Mid Layer 4 w6: v3(462.13,253.97) 476.41,253.97 v1(486.22,263.78)
PALDO: C62.1 C63.2 U21.8 U21.10 U21.12 | length 210.5
  Top Layer w7.87: C63.2@830.17,1579.73 839.41,1570.48 v2(863.19,1570.48) 863.19,1561.19 887.8,1536.58 U21.12@887.8,1526.57
  Mid Layer 1 w9.84: v5(863.19,1552.47) v2(863.19,1570.48) ; v5(901.29,1518.7) v2(919.29,1518.7) v2(950.79,1518.7)
  Mid Layer 2 w9.84: v5(863.19,1552.47) 896.96,1518.7 v5(901.29,1518.7)
PVSS1: C9.1 C47.1 C52.1 NT1.2 U11.2 | length 55.5
  Bottom Layer w7.87: v1(552.17,1719.49) v1(552.17,1740.16) ; 574.8,1750 C47.1@599.41,1725.39
PVSS2: C48.1 C53.1 C74.1 NT2.2 U11.6 | length 132.5
  Bottom Layer w7.87: C48.1@599.41,1569.88 596.46,1566.93 v1(596.46,1540.35) v1(596.46,1522.64) 604.33,1514.76 640.75,1514.76 C53.1@649.61,1523.62 641.73,1531.5 NT2.2@628.94,1531.5
PWRIOVDD: C41.2 C42.2 U21.1 U21.34 | length 480
  Top Layer w6: U21.34@1029.53,1290.35 1029.89,1290 1029.89,1276.15 1076.7,1229.33 v2(1073.82,1229.33)
  Top Layer w10: U21.1@1061.02,1526.57 1061.02,1541.23 1078.47,1558.67 v2(1081.42,1558.67) 1082.01,1558.67 1082.33,1558.35 C41.2@1082.33,1557.76 ; C41.2@1080.52,1557.76 1080.52,1558.35 C41.2@1080.83,1558.67
  Mid Layer 1 w9.84: v2(1073.82,1229.33) v5(1091.82,1229.33) ; v5(1081.42,1540.67) v2(1081.42,1558.67)
  Mid Layer 2 w9.84: v5(1081.42,1540.67) 1091.82,1530.26 v5(1091.82,1229.33)
QSPI_CLK: M1.73 U6.L12 U7.E3 U18.13 U21.35 | length 2338.8
  Top Layer w4.92: v2(472.96,871.33) v2(502.53,871.33) ; U21.35@1045.28,1290.35 1045.28,1276.57 1053.15,1268.7 1064.16,1268.7 v2(1111.62,1268.7)
  Mid Layer 1 w4.92: v2(472.96,871.33) 472.96,865.11 474.06,864.02 474.06,659.19 485.06,648.19 530.92,648.19 581.71,597.4 581.71,583.18 v2(595.98,568.9) v5(612.6,568.9) ; v2(502.53,871.33) 508.7,877.51 564.46,877.51 576.71,889.76 ; v2(1111.62,1268.7) v5(1127.02,1253.3)
  Mid Layer 1 w5: 576.71,889.76 736.33,889.76 779.73,933.16 779.73,968.63 v2(796.48,985.38)
  Mid Layer 2 w5: v5(612.6,568.9) 720.81,568.9 840.46,688.55 840.46,700.36 853.38,713.27 868.84,713.27 876.49,705.63 v4(911.6,705.63)
  Mid Layer 2 w5.91: v5(1127.02,1253.3) 1134.57,1245.75 v4(1134.57,1216.82)
  Mid Layer 3 w4.92: v4(610.98,854.87) 610.98,810.13 628.93,792.17 628.93,745.56 635.67,738.82 635.67,725.14 646.35,714.46 681.71,714.46 720.91,675.25 720.91,657.45 730.21,648.15 760.12,648.15 772.15,636.13 v4(772.15,619.23) ; v3(1129.95,967.86) 1129.95,1212.21 v4(1134.57,1216.82)
  Mid Layer 4 w4.92: v1(599.51,876.64) 610.98,865.17 v4(610.98,854.87) ; v7(912.4,680.12) 911.6,680.92 v4(911.6,705.63) 911.6,756.74 923.98,769.12 973.07,769.12 988.47,784.52 988.47,814.93 1129.95,956.41 v3(1129.95,967.86)
  Bottom Layer w5.91: v1@599.39,879.52 U6.L12@599.39,890.95
QSPI_SS: M1.78 U6.J7 U21.36 | length 1759.6
  Top Layer w4.92: U21.36@1061.02,1284.45 v2(1123.89,1284.45)
  Mid Layer 1 w4.92: v2(595.98,470.47) 618.77,470.47 v5(630.15,481.85) ; v2(1123.89,1284.45) 1128.32,1280.02 v5(1157.96,1280.02)
  Mid Layer 2 w4.92: v5(1157.96,1280.02) 1159.11,1280.02 1169.99,1269.15 v4(1169.99,1232.94)
  Mid Layer 2 w5: v5(630.15,481.85) 735.78,481.85 849.04,595.11 v4(849.04,613.15)
  Mid Layer 3 w4.92: v3(674.4,894.17) 674.4,876.93 683.45,867.87 683.45,834.8 638.79,790.14 638.79,757.44 646.72,749.51 660.64,749.51 733.49,676.65 797.95,676.65 849.04,625.56 v4(849.04,613.15) 913.91,613.15 983.12,682.36 983.12,715.53 993.75,726.16 997.81,726.16 1005.89,734.24 1005.89,796.15 v3(1036.04,826.29) ; v3(1158.02,967.86) 1158.02,1159.2 1178.61,1179.79 1178.61,1224.32 v4(1169.99,1232.94)
  Mid Layer 4 w4.92: v7(668.29,929.5) 674.4,923.4 v3(674.4,894.17) ; v3(1036.04,826.29) 1036.04,833.62 1158.02,955.6 v3(1158.02,967.86)
  Bottom Layer w4.92: U6.J7@668.29,918.5 v7(668.29,929.5)
RESET: P8.10 U1.3 | length 376.1
  Mid Layer 2 w5.91: v6(359.25,281.89) 470.37,281.89 v4(524.15,335.67)
  Mid Layer 3 w5.91: v4(524.15,335.67) 560.59,335.67 607.76,382.84 v3(607.76,406.65)
  Mid Layer 4 w5.91: v3(607.76,406.65) 608.65,405.76 v7(669.4,405.76)
RF1: U17.2 Z3.1
RF2: U17.8 Z1.1
RF3: U17.9 Z2.1
RF4: U17.1 Z4.1
RFC: U17.10 Z5.2
RFFE_BLE_WIFI_ENABLE: U5.B2 U6.K7 U11.8 | length 1668.4
  Mid Layer 2 w4.92: v4(551.01,1532.33) 562.01,1521.33 562.01,1476.78 498.11,1412.89 438.81,1412.89 399.29,1373.36 399.29,1327.31 365.5,1293.53 365.5,1264.12 364.72,1263.34 364.72,1201.21 432.04,1133.89 541.69,1133.89 570.38,1105.2 589.19,1105.2 601.79,1092.59 601.79,1087.3 654.8,1034.3 654.8,998.07 562.23,905.5 v4(562.23,796.36)
  Mid Layer 3 w4.92: v4(551.01,1532.33) 552.8,1530.54 791.37,1530.54 v3(824.8,1563.98)
  Mid Layer 4 w4.92: v1(521.65,1553.71) 529.63,1553.71 v4(551.01,1532.33) ; v4@552.01,1533.33 v4@553.01,1532.33 ; v4(562.23,796.36) 582.71,816.84 v7(594.71,816.84) ; v3(824.8,1563.98) 854.27,1593.45 v1(864.61,1593.45)
  Bottom Layer w4.92: v1(521.65,1553.71) U11.8@521.65,1568.9 ; v7(594.71,816.84) 594.78,816.77 605.4,816.77 642.67,854.04 642.67,879.11 U6.K7@668.29,904.72 ; v1(864.61,1593.45) U5.B2@864.61,1610.18
RST: D3.1 J4.C2 | length 118.5
  Mid Layer 1 w5.91: v4(998.03,92.13) 1009.84,103.94 v9(1009.84,113.78)
  Mid Layer 4 w5.91: v4(998.03,92.13) 1015.75,109.84 1043.11,109.84 v1(1071.06,137.8)
SCL: M1.67 R22.2 SB8.2 TP9.1 U6.J11 U11.14 U20.4 U23.4 U25.E3 U26.A3 | length 4687.9
  Top Layer w4.92: SB8.2@255.69,617.57 288.33,650.21 v2(364.05,650.21) ; v2(376.98,1086.81) 524.98,1086.81 v2(558.2,1120.03)
  Top Layer w5: v2(645.2,929.84) U26.A3@645.2,961.86
  Mid Layer 1 w4.92: v2(340.26,876.52) 340.26,893.57 v5(378.83,932.15) ; v5(358.03,1086.81) v2(376.98,1086.81) ; v2(364.05,650.21) v5(403.5,650.21) ; v2(445.78,592.51) v5(445.78,616.75) ; v2(595.98,687.01) v5(613.63,669.36)
  Mid Layer 1 w5: v4(410.43,929.13) 422.02,929.13 426.5,924.65 527.2,924.65 540.48,937.94 556.06,937.94 564.16,929.84 v2(645.2,929.84) ; v2(558.2,1120.03) 573.95,1104.28 590.26,1104.28 620.37,1074.18 664.01,1074.18 v2(678.7,1059.5)
  Mid Layer 2 w4.92: v5(378.83,932.15) 378.83,932.22 349.9,961.15 349.9,1078.68 v5(358.03,1086.81) 349.9,1094.94 349.9,1154.32 305.12,1199.1 305.12,1338.58 380.41,1413.88 380.41,1457.39 v4(394.68,1471.66) ; v5@380.06,931 408.57,931 v4(410.43,929.13) 410.43,894.66 403.54,887.77 403.54,650.26 v5(403.5,650.21) 403.5,638.32 409.81,632.01 430.52,632.01 v5(445.78,616.75) 454.6,607.93 589.46,607.93 602.44,620.9 602.44,658.16 v5(613.63,669.36)
  Mid Layer 3 w4.92: v3(617.97,1298.68) 629.3,1310 629.3,1406.13 596.65,1438.78 427.56,1438.78 v4(394.68,1471.66) 394.68,1480.43 433.86,1519.61 537.11,1519.61 541.63,1515.08 559.68,1515.08 564.21,1519.61 801.95,1519.61 884.84,1602.5 884.84,1669.33 916.91,1701.4 1168.06,1701.4 1228.3,1761.64 1228.3,1829.67 1308.07,1909.45 1317.91,1919.29 1372.42,1919.29 1393.31,1898.41 1484.88,1898.41 1508.86,1922.39 1508.86,2026.43 v3(1498.03,2037.26) ; v3(769.96,1341.45) 770.05,1341.54 v3(866.03,1341.54)
  Mid Layer 4 w4.13: 647.47,1272 664,1272 669.17,1266.84 695.35,1266.84 717.97,1289.46
  Mid Layer 4 w4.21: v7(632.87,1321.85) 621.21,1309.29 618.15,1305.99 617.97,1305.82 v3(617.97,1298.68) 617.97,1290.36 636.33,1272 647.47,1272
  Mid Layer 4 w4.92: v4(410.43,929.13) 465.55,929.13 v1(485.24,909.45) ; 717.97,1289.46 v3(769.96,1341.45) ; v3(866.03,1341.54) v1(882.97,1341.54) ; v3(1498.03,2037.26) v1(1498.03,2055.57)
  Mid Layer 4 w5.91: v4@394.68,1473.63 v1(394.68,1494.09)
  Bottom Layer w4.13: 561.01,884.55 565.71,884.55 595.44,914.27 608.35,914.27 608.94,914.86 609.47,914.86 U6.J11@613.17,918.5 U6.J11@613.17,918.5
  Bottom Layer w4.92: v1(485.24,909.45) 510.14,884.55 561.01,884.55 ; v1(882.97,1341.54) U20.4@883.27,1341.54
  Bottom Layer w5.91: v1@395.67,1498.03 U11.14@395.67,1541.34
SCLK: R28.2 TP26.1 U17.6 | length 968
  Top Layer w7.87: U17.6@1311.75,232.27 1329.43,232.27 1348.33,251.16 v6(1371.64,251.16)
  Mid Layer 4 w4.92: 1091.7,688.98 v1(1140.68,688.98)
  Bottom Layer w4.92: TP26.1@1120.47,858.07 1120.47,772.1 1140.75,751.83 1140.75,746.62 ; v1(1140.68,688.98) 1140.75,688.98 1140.75,746.62 ; v6(1371.64,251.16) 1364.33,258.47 1364.33,664.13 1325.33,703.13 1221.6,703.13 1178.11,746.62 1140.75,746.62
  other v1: 1086.61,685.04
SDA: M1.68 R23.2 SB9.2 TP10.1 U6.K12 U11.13 U20.2 U23.3 U25.E2 U26.A2 | length 4453.1
  Top Layer w4.92: SB9.2@255.69,664.23 351.62,664.23 v2(351.9,664.52) 351.9,693.98 340.26,705.62 TP10.1@340.26,745.17
  Top Layer w6: v2(660.95,911.95) U26.A2@660.95,961.86
  Mid Layer 1 w4.92: v2(351.9,664.52) 389.24,664.52 v5(389.44,664.32) ; v2(422.16,592.51) v5(422.16,616.75) ; v2(595.98,667.32) v5(616.27,647.03)
  Mid Layer 1 w6: v4(387.89,900.98) 400.18,888.69 457.03,888.69 468.07,899.73 554.88,899.73 567.1,911.95 v2(660.95,911.95)
  Mid Layer 2 w4.92: v4(421.01,1481.99) 414.12,1488.88 387.55,1488.88 370.57,1471.9 370.57,1417.95 295.28,1342.66 295.28,1195.02 340.06,1150.24 340.06,948.81 386.89,901.98 v4(387.89,900.98) 393.7,895.17 393.7,668.58 v5(389.44,664.32) 389.44,633.69 406.38,616.75 v5(422.16,616.75) 441.14,597.76 594.72,597.76 616.27,619.31 v5(616.27,647.03)
  Mid Layer 3 w4.92: v3(639.86,1291.37) 639.86,1409.49 600.73,1448.62 434.3,1448.62 421.01,1461.92 v4(421.01,1481.99) 448.19,1509.17 533.28,1509.17 537.62,1504.83 563.97,1504.83 568.31,1509.17 807.31,1509.17 894.68,1596.55 894.68,1665.26 918.13,1688.7 1170,1688.7 1238.37,1757.07 1238.37,1825.83 1321.99,1909.45 1367.91,1909.45 1389.49,1887.87 1489.39,1887.87 1518.7,1917.18 1518.7,2026.43 v3(1529.53,2037.26) ; v3(757.19,1355.67) 873.13,1355.67 v3(897.81,1380.34)
  Mid Layer 4 w4.13: v3(639.86,1291.37) 650.38,1280.85 670.21,1280.85 674.24,1276.81 690.63,1276.81 717.97,1304.16
  Mid Layer 4 w4.92: v4(387.89,900.98) 406.64,900.98 422,916.34 458.66,916.34 v1(484.25,890.75) ; 717.97,1304.16 750.42,1336.61 750.42,1348.9 v3(757.19,1355.67) ; v3(897.81,1380.34) v1(914.26,1380.34) ; v3(1529.53,2037.26) v1(1529.53,2055.57)
  Mid Layer 4 w5.91: v1(417.32,1504.92) 417.32,1485.68 v4(421.01,1481.99)
  Mid Layer 4 w6: v7(632.87,1305.32) 632.87,1298.35 v3(639.86,1291.37)
  Bottom Layer w4.13: 561.01,874.7 574.52,874.7 583.06,883.24 583.06,888.39 U6.K12@599.39,904.72
  Bottom Layer w4.92: v1(484.25,890.75) 485.24,890.75 501.28,874.7 561.01,874.7 ; U20.2@883.27,1380.91 913.69,1380.91 v1(914.26,1380.34)
  Bottom Layer w5.91: U11.13@415.35,1541.34 415.35,1506.89 v1(417.32,1504.92)
SDATA: R27.2 TP34.1 U17.5 | length 1040.1
  Top Layer w7.87: U17.5@1311.75,216.52 1332.39,216.52 1339.29,223.43 v6(1364.88,223.43)
  Mid Layer 4 w4.92: v1(1020.47,787.08) 1013.09,779.7 1013.09,696.54 1045.26,664.37 v1(1086.61,664.37) ; v1@1086.61,665.35 1096.46,675.2 v1(1126.97,675.2)
  Bottom Layer w4.92: v1(1020.47,787.08) TP34.1@1020.47,858.07 ; v1(1126.97,675.2) 1151.01,675.2 1168.68,692.86 1319.75,692.86 1353.7,658.92 1353.7,264.43 1353.7,234.6 v6(1364.88,223.43)
Shield: C101.2 C102.2 J6.SHLD
SHPHLD: Q6.5 SW4.1 U11.15 | length 821.1
  Mid Layer 2 w4.92: v4(369.09,1805.65) 369.09,1780.76 397.15,1752.71 397.15,1710.82 408.14,1699.83 408.14,1525.72 v4(398.42,1516)
  Mid Layer 4 w4.92: v4@369.09,1807.62 v1(369.09,1827.35)
  Mid Layer 4 w5.91: v1(375.98,1516) v4(398.42,1516)
  Bottom Layer w4.92: SW4.1@159.45,1999.02 194.39,1964.07 263.6,1964.07 298.54,1999.02 301.18,1999.02 295.28,1993.11 295.28,1934.96 ; Q6.5@272.8,1935.22 295.02,1935.22 295.28,1934.96 ; v1(369.09,1827.35) 369.09,1838.88 375.98,1845.77 375.98,1894.68 368.6,1902.07 300.18,1902.07 295.28,1906.97 295.28,1934.96
  Bottom Layer w5.91: v1(375.98,1516) U11.15@375.98,1541.34
SIM.1V8: C34.2 M1.19 R49.2 U16.14 U16.16 | length 320.9
  Top Layer w7.87: v2(1063.37,343.5) 1065.35,343.5 1108.04,300.82 1108.04,286.15 ; U16.14@1087.6,241.14 1125.39,241.14 1125.98,240.55 1125.98,268.2 1108.04,286.15 ; U16.16@1087.6,272.64 1094.52,272.64 1108.04,286.15
  Mid Layer 1 w7.87: v2(965.08,396.65) 965.08,386.6 v5(975.41,376.27) ; v5(1047.37,343.5) v2(1063.37,343.5)
  Mid Layer 2 w7.87: v5(975.41,376.27) 1008.18,343.5 v5(1047.37,343.5)
SIM.CLK: M1.18 U16.8 | length 200.5
  Top Layer w5.91: v2(975.78,286.8) 970.47,281.5 970.47,236.09 981.16,225.39 U16.8@991.14,225.39
  Mid Layer 1 w5.91: v5(945.38,379.06) v2(945.38,396.65) ; v2(975.78,286.8) v5@975.78,305.28
  Mid Layer 2 w5.91: v5(945.38,379.06) 945.38,359.7 955.45,349.63 955.45,341.91 975.75,321.61 v5(975.75,305.31)
SIM.IO: M1.17 U16.4 | length 197.6
  Top Layer w5.91: v2(1007.75,297.53) 1015.75,289.54 U16.4@1015.75,281.5
  Mid Layer 1 w5.91: v2(925.69,396.65) v5(925.69,416.1) ; v5(995.92,309.37) v2(1007.75,297.53)
  Mid Layer 2 w5.91: v5(925.69,416.1) 925.69,411.28 940.72,396.26 951.46,396.26 959.86,387.86 959.86,363.44 992.04,331.26 992.04,313.24 v5(995.92,309.37)
SIM.RST: M1.16 U16.12 | length 327.1
  Top Layer w5.91: v2(906.01,396.65) M1.16@906.18,396.65 ; v2(959.64,296.79) 959.64,223.43 988.19,194.88 1051.31,194.88 1059.45,203.02 1059.45,203.15 1061.61,205.31 1061.61,205.95 1062.99,207.33 U16.12@1062.99,216.54
  Mid Layer 1 w5.91: v5(906.01,379.73) v2(906.01,396.65) ; v2(959.64,296.79) v5(959.64,313.01)
  Mid Layer 2 w5.91: v5(906.01,379.73) 908.56,379.73 942.73,345.57 942.73,329.93 v5(959.64,313.01)
SW0: L9.1 U25.J4 | length 156.3
  Bottom Layer w7.87: 559.06,1345.47 566.14,1338.39 U25.J4@571.46,1338.39
  Bottom Layer w11.81: L9.1@454.73,1413.39 497.05,1371.06 540.9,1371.06 552.17,1359.8 552.17,1352.36 562.01,1342.52
SW1: L7.2 U11.3 | length 171.3
  Bottom Layer w11.81: U11.3@521.65,1667.32 545.28,1667.32 576.77,1698.82 655.12,1698.82 671.26,1682.68 L7.2@673.23,1682.68
SW2: L8.2 U11.5 | length 149.9
  Bottom Layer w11.81: U11.5@521.65,1627.95 545.28,1627.95 576.77,1596.46 657.09,1596.46 L8.2@658.07,1597.44
SW3: L10.1 U25.J2 | length 124.3
  Bottom Layer w7.87: 559.06,1298.23 566.14,1305.32 U25.J2@571.46,1305.32
  Bottom Layer w11.81: L10.1@477.36,1252.95 497.05,1272.64 540.9,1272.64 552.17,1283.9 552.17,1291.34 562.01,1301.18
SW_CTRL1: R60.2 U21.45 | length 40.5
  Top Layer w4.92: U21.45@1092.52,1447.83 1106.67,1447.83 R60.2@1132.99,1447.83
SWD1_CLK: R4.1 U6.L1 | length 39.7
  Bottom Layer w4.13: U6.L1@750.97,890.95 771.84,870.07 R4.1@771.84,859.84
SWD1_IO: R6.1 U6.H1 | length 104.3
  Bottom Layer w4.13: U6.H1@750.97,932.28 754.83,932.28 816.66,870.45 816.66,867.13 822.48,861.32 R6.1@822.48,859.84
SWD1_RESET: R16.1 U6.G3 | length 217.5
  Mid Layer 4 w4.92: v7(723.41,946.06) 707.53,946.06 701.51,940.04 701.51,923.73 722.89,902.35 753.24,902.35 760.53,909.64 796.58,909.64 v1(827.38,878.85)
  Bottom Layer w4.92: v1(827.38,878.85) 844.97,861.25 R16.1@844.97,859.84
SWDCLK: P8.4 TP27.1 U12.4 | length 740.7
  Top Layer w5.91: P8.4@286.81,419.86 275.98,409.04 275.98,261.97 292.08,245.87 324.8,245.87 cw(c324.8,192.91) 362.25,230.36 375.08,217.52 493.11,217.52 TP27.1@531.5,255.91 536.54,255.91 592.06,311.43 v6(592.06,318.34) ; P8.4@286.81,419.88 298.82,431.89 P8.4@323.82,431.89
  Bottom Layer w5.91: v6(592.06,318.34) 602.64,328.92 719.86,328.92 730.31,318.47 U12.4@730.31,307.09
SWDIO: P8.2 TP29.1 U12.16 | length 763.8
  Top Layer w5.91: P8.2@323.82,481.89 298.82,481.89 265.16,448.23 265.16,257.48 287.6,235.04 324.8,235.04 cw(c324.8,192.91) 354.59,222.7 370.6,206.69 600.39,206.69 TP29.1@649.61,255.91 642.73,262.78 v6(642.73,308.46)
  Bottom Layer w5.91: v6@641.73,308.46 651.97,298.23 U12.16@658.46,298.23
SXLDO: C61.2 U21.11 | length 51.3
  Top Layer w6: C61.2@885.63,1570.48 885.97,1570.14 885.97,1556.7 902.61,1540.07 903.18,1539.49 903.18,1526.93 U21.11@903.54,1526.57
USB.D_N: C99.1 R31.1 U6.A11 | length 285.6
  Bottom Layer w3.27: R31.1@416.21,1046.57 C99.1@416.21,1026.38 414.75,1024.91 ccw(c427.47,1012.19) 409.48,1012.19 ccw(c424.45,1012.19) 413.86,1001.6 415.91,999.56 ccw(c421.82,1005.47) 421.82,997.11 429.92,997.11 ccw(c429.92,1037.66) 437.22,997.77 ccw(c429.92,1037.66) 458.6,1008.98 ccw(c455.9,1011.69) 459.72,1011.69 459.72,1024.05 cw(c479.66,1024.05) 465.56,1038.15 468.2,1040.79 cw(c485.6,1023.39) 485.6,1048 578.19,1048 cw(c578.19,1010.06) 605.02,1036.89 U6.A11@613.17,1028.74
USB.D_P: C100.1 R34.1 U6.A12 | length 282.1
  Bottom Layer w3.27: R34.1@394.47,1046.57 C100.1@394.47,1026.38 395.93,1024.91 cw(c383.21,1012.19) 401.2,1012.19 ccw(c424.45,1012.19) 408.01,995.75 410.06,993.71 ccw(c421.82,1005.47) 421.82,988.83 431.48,988.83 ccw(c431.48,1033.89) 438.1,989.32 ccw(c431.48,1033.89) 463.35,1002.03 464.45,1003.13 ccw(c455.9,1011.69) 467.99,1011.69 467.99,1024.05 cw(c479.66,1024.05) 471.4,1032.29 474.05,1034.94 cw(c485.6,1023.39) 485.6,1039.73 578.19,1039.73 cw(c578.19,1015.08) 595.62,1032.51 U6.A12@599.39,1028.74
VBAT: C51.2 J3.3 TP4.1 U11.19 | length 775
  Top Layer w19.68: TP4.1@275.59,1929.13 285.94,1918.79 280.28,1913.13 292.51,1913.13 v6(324.04,1881.61)
  Mid Layer 2 w19.68: v4(134.66,1531.17) 134.66,1634.22 110.1,1658.78 110.1,1793.22 211.56,1894.69 310.96,1894.69 v6(324.04,1881.61)
  Mid Layer 4 w19.68: v4(134.66,1531.17) v1(175.46,1531.17)
  Bottom Layer w19.68: v1(157.86,1531.17) v1(175.46,1531.17) 225.27,1531.17 252.16,1558.06 C51.2@252.16,1562.99 ; v6(324.04,1881.61) 324.32,1881.89 J3.3@334.65,1881.89
VBAT_nRF70: C64.2 C67.1 C68.2 C73.2 P9.2 TP13.1 U2.A1 U21.13 U21.20 U21.25 U21.31 | length 2507.5
  Top Layer w5.51: C73.2@800.2,1373.23 802.17,1373.23 813.78,1384.84 U21.20@856.3,1384.84
  Top Layer w6: 883.19,1290.35 U21.25@887.8,1290.35
  Top Layer w9.06: C68.2@811.14,1525.59 811.14,1516.42 812.2,1515.35 821.38,1515.35 841.65,1495.08 U21.13@856.3,1495.08
  Top Layer w10: v9(479.2,1152.68) TP13.1@492.13,1139.76 ; C73.2@793.11,1366.14 785.83,1358.86 785.83,1298.82 794.29,1290.35 v2(856.3,1290.35) 883.19,1290.35 ; U21.31@982.28,1290.35 982.28,1250.87 982.28,1221.69 C67.1@982.63,1221.35
  Top Layer w15.75: C68.2@798.78,1529.76 C68.2@801.97,1526.57
  Mid Layer 1 w9.84: v2(801.69,1528.15) v5(814.42,1515.42) ; v2(856.3,1290.35) v5(856.3,1308.36) ; v2(981.65,1250.87) v5(981.65,1268.88)
  Mid Layer 1 w10: v4(446.18,1185.94) 446.18,1185.71 v9(479.2,1152.68)
  Mid Layer 2 w9.84: v5(814.42,1515.42) 828.27,1501.57 828.27,1336.39 v5(856.3,1308.36) 874.3,1290.35 960.17,1290.35 v5(981.65,1268.88)
  Mid Layer 2 w19.68: v4(438.57,1254.92) 461.37,1254.92 575.54,1140.75 745.85,1140.75 776.57,1171.48 776.57,1317.91
  Mid Layer 3 w10: 366.05,1184.06 367.94,1185.94 v4(446.18,1185.94)
  Mid Layer 3 w19.68: 184.76,279.53 165.35,298.93 165.35,827.76 366.05,1028.46 366.05,1184.06 366.05,1211.61
  other v1: 130.9,279.53 147.64,279.53 164.37,279.53 181.1,279.53 339.57,1247.05 356.3,1247.05 339.57,1263.78 356.3,1263.78
  other v3: 196.85,279.53 213.58,279.53 230.32,279.53 247.05,279.53 372.5,1246.85 390.22,1246.85 372.5,1263.58 390.22,1263.58
  other v4: 410.43,1254.92
  other v5: 767.72,1318.9 784.45,1318.9 767.72,1336.61 784.45,1336.61
  other v9: 767.72,1282.48 784.45,1282.48 767.72,1300.2 784.45,1300.2
VBUS: C44.2 C46.2 FB2.2 U11.21 | length 160.8
  Mid Layer 3 w19.68: v3@209.65,1522.64 209.65,1648.62 234.25,1673.23
  other v1: 210.63,1501.97 227.36,1501.97 244.1,1501.97 260.83,1501.97 235.79,1657.54 252.52,1657.54 269.26,1657.54 235.79,1675.26 252.52,1675.26
  other v3: 210.63,1517.72 227.36,1517.72 244.1,1517.72 260.83,1517.72 269.26,1671.26 235.79,1687.99 252.52,1687.99 269.26,1687.99
VBUS_CONN: C11.2 C14.2 C43.2 FB2.1 J6.A4 J6.A9 TP12.1 U8.1 | length 327.6
  Top Layer w15.75: v6(322.83,1325.79) 322.83,1309.05 TP12.1@374.02,1257.87
  Bottom Layer w15.75: 309.55,1324.8 310.53,1325.79 v6(322.83,1325.79)
  Bottom Layer w19.68: FB2.1@252.95,1477.36 274.61,1477.36 309.55,1442.42 309.55,1324.8 309.55,1297.74 v1(305.12,1293.31) v1@303.15,1291.34
  other v1: 313.29,1124.85 330.02,1124.85 330.02,1141.58 346.76,1141.58 254.92,1293.31 271.65,1293.31 288.38,1293.31
  other v3: 296.56,1108.12 313.29,1108.12 296.56,1124.85 296.56,1141.58 313.29,1141.58 254.92,1277.56 271.65,1277.56 288.39,1277.56 305.12,1277.56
